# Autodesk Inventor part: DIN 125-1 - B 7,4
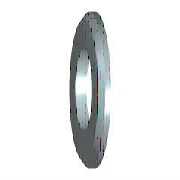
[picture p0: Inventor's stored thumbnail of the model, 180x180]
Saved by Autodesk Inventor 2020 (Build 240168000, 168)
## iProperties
IsCustomPart: 0
Created: 2007-03
Part Number: DIN 125-1 - B 7,4
Cost Center: 0 kg
Material: Steel, Mild
Document SubType Name: Modeling
Standard: DIN 125-1
Designer: Administrator
Authority: 174 mm^3
Standards Organization: DIN
Language: de-DE
Size Designation: B 7,4
Categories: <MemberInstance><Categories><Category DisplayName="Schrauben" InternalName="e4da775c-781d-43d5-af7c-5136215cf5a6" Mnemonic="FSTN"><Category DisplayName="Unterle
Mass: 1.36792 g
Surface Area: 3.18914 cm^2
Volume: 0.174036 cm^3
Density: 7.86 g/cm^3
Appearance: Stahl
SaveDate: 2007-08-01
SaveTime: 08:51
TotalMass: 0 kg
TotalVolume: 174 mm^3
Author: Administrator
Revision Number: C
Title: Unterlegscheibe
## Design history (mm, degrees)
workaxis "Work Axis1"
workplane "Work Plane1"
node "Center of Mass"
node "Volumenkörper1"
sketch "Skizze"
  geometry: C1 r 7 at (0, 0); C2 r 3.7 at (0, 0); 1 further point
  constraints: 2 centre point, 2 coincident
  dimensions: "d0" = 7.4 diameter of C2 (= SD1); "d1" = 14 diameter of C1 (= SD2)
extrude "Körper" new body sketch "Skizze" distance "d2" = 1.6 (= SD); taper "d3" = 0 deg
node "Volumenkörpern"
node "Oberflächenkörpern"
chamfer "Fase" distance "d4" = 0.4 (= PHH); stored, may be unused: angle "d5" = 45 deg, second distance "d8" = 0.4 (= PHH)
other parameters: "SD1" = 7.4 [user parameter; used in 1 equation term], "SD2" = 14 [user parameter; used in 1 equation term], "SD" = 1.6 [user parameter; used in 1 equation term], "PHH" = 0.4 [user parameter; used in 2 equation terms], "FAWI" = 45 deg [user parameter], "d6" = 0, "d7" = 0, "d9" = 0, "d10" = 0, "NND" = 7 [user parameter]
